// Mitsubishi GX Works2 project: 12.自动延时断电   PLC: FX3U/FX3UC

PROGRAM MAIN
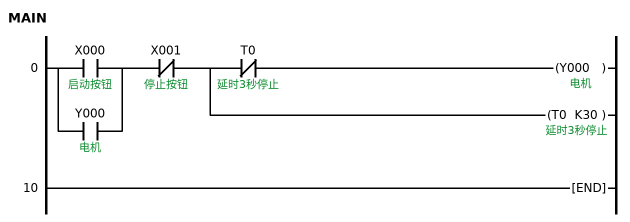
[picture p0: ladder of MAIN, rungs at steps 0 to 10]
0     LD      X000  ; 启动按钮
      OR      Y000  ; 电机
      ANI     X001  ; 停止按钮
      MPS
      ANI     T0  ; 延时3秒停止
      OUT     Y000  ; 电机
      MPP
      OUT     T0 K30  ; 延时3秒停止
10    END
END_PROGRAM
